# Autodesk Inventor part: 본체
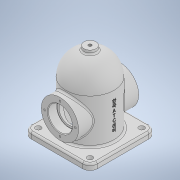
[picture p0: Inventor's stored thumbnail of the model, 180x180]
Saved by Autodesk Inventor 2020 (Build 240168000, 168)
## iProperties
Created: 2021-07
Part Number: 본체
Material: 일반
Document SubType Name: Modeling
Designer: Owner
Mass: 320.706 g
Surface Area: 800.746 cm^2
Volume: 320.706 cm^3
Density: 1 g/cm^3
Appearance: 기본값
Author: Owner
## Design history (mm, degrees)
sketch "스케치1"
  geometry: C1 r 40 at (0, 0); 1 further point
  constraints: 1 centre point, 1 coincident
  dimensions: "d0" = 80 diameter of C1
extrude "돌출1" new body sketch "스케치1" distance "d1" = 124; taper "d2" = 0 deg
fillet "모깎기1" dims "d3" = 40
feature "쉘1" dims "d4" = 8
sketch "스케치2"
  geometry: L1 (55, 55)-(-55, 55); L2 (-55, 55)-(-55, -55); L3 (-55, -55)-(55, -55); L4 (55, -55)-(55, 55); L5 (55, 55)-(-55, -55); L6 (-55, 55)-(55, -55); 1 further point
  constraints: 12 end point, 2 midpoint, 2 parallel, 1 horizontal, 1 perpendicular
  dimensions: "d5" = 110 distance of L3.end L2.end; "d6" = 110 distance of L2.end L1.end
extrude "돌출2" join sketch "스케치2" distance "d7" = 10; taper "d8" = 0 deg
node "작업 평면1"
sketch "스케치3"
  geometry: L1 (-55, 0)-(55, 0) reference; 3 further points
  constraints: 1 midpoint, 1 vertical alignment
  dimensions: "d9" = 48 distance from line of L1 point (0, 48)
sketch "스케치4"
  geometry: C1 r 32 at (0, 0) reference; 1 further point
extrude "돌출3" cut sketch "스케치4" extent not by distance; stored distance "d10" = 114; taper "d11" = 0 deg
node "작업 평면2"
sketch "스케치6"
  geometry: C1 r 31 at (0, 48); 2 further points
  constraints: 1 centre point, 1 coincident
  dimensions: "d13" = 62 diameter of C1
extrude "돌출4" join sketch "스케치6" stored distance "d14" = 10; taper "d15" = 0 deg
sketch "스케치7"
  geometry: C1 r 31 at (0, 0) reference; 2 further points
  constraints: 1 coincident
hole "구멍1" sketch "스케치7" at (0, 0) diameter "d16" = 33; stored, may be unused: countersink angle "d20" = 90 deg, drill point angle "d22" = 0 deg; dims "d17" = 6, "d18" = 40, "d19" = 15, "d21" = 8
fillet "모깎기2" dims "d23" = 0.3
chamfer "모따기1" distance "d24" = 1; stored, may be unused: second distance "d25" = 2, angle "d26" = 45 deg
sketch "스케치8"
  geometry: C1 r 16.5 at (0, 0) reference; 2 further points
  constraints: 1 vertical alignment
  dimensions: "d27" = 25.5 distance of C1.centre point (0, 25.5)
hole "구멍2" sketch "스케치8" at (0, 25.5) diameter "d28" = 3.242; stored, may be unused: countersink angle "d32" = 90 deg, drill point angle "d34" = 118 deg; dims "d29" = 8, "d30" = 40, "d31" = 15, "d33" = 10
fillet "모깎기3" dims "d38" = 12
fillet "모깎기4" dims "d39" = 3
fillet "모깎기5" dims "d40" = 3
sketch "스케치9"
  geometry: A1 r 9 centre (43, -43) between (43, -52) and (52, -43) reference; 2 further points
  constraints: 1 coincident
hole "구멍3" sketch "스케치9" at (43, -43) diameter "d41" = 9; stored, may be unused: countersink angle "d45" = 90 deg, drill point angle "d47" = 118 deg; dims "d42" = 8, "d43" = 40, "d44" = 15, "d46" = 10
node "작업 평면3"
sketch "스케치10"
  geometry: C1 r 10 at (0, 0); 1 further point
  constraints: 1 centre point, 1 coincident
  dimensions: "d49" = 20 diameter of C1
extrude "돌출5" join sketch "스케치10" stored distance "d50" = 10; taper "d51" = 0 deg
sketch "스케치11"
  geometry: C1 r 10 at (0, 0) reference; 2 further points
  constraints: 1 coincident
hole "구멍4" sketch "스케치11" at (0, 0) diameter "d52" = 5.1881; stored, may be unused: countersink angle "d56" = 90 deg, drill point angle "d58" = 0 deg; dims "d53" = 12, "d54" = 40, "d55" = 15, "d57" = 16
fillet "모깎기6" dims "d59" = 3
node "작업 평면4"
sketch "스케치12"
  geometry: L1 (0, 43)-(0, -43) reference; 3 further points
  constraints: 1 horizontal alignment, 1 midpoint, 1 other
  dimensions: "d60" = 48 distance from line of L1 point (48, 0)
feature "엠보싱1" sketch "스케치12" dims "d2" = 0, "d61" = 0.5, "d62" = 0
node "솔리드1"
mirror "미러1"
pattern_circular "원형 패턴1" dims angle "d36" = 360 deg
mirror "미러2"
mirror "미러3"
mirror "미러4"
node "투영된 루프1"
feature "A9D066F2-1C7D-4E18-AEED-F7BC21143FA4" dims "d16" = 33, "d17" = 6, "d18" = 40, "d19" = 15, "d20" = 90 deg, "d21" = 8, "d22" = 0
other parameters: "d48" = 129
